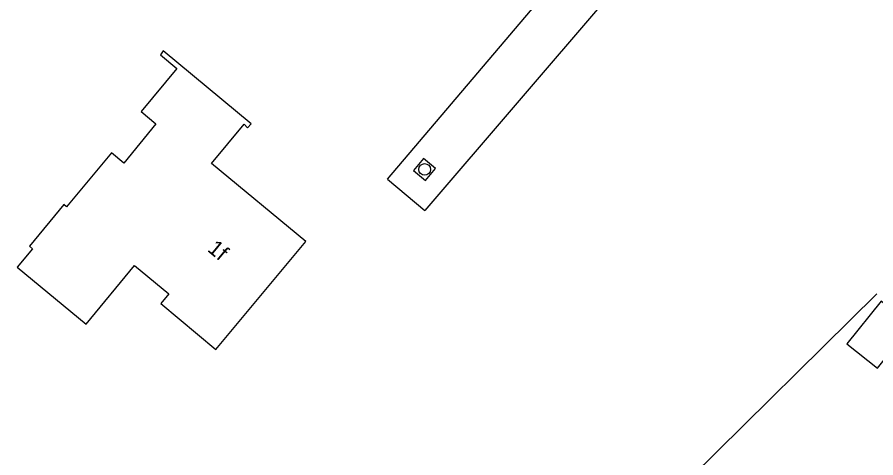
# Model space of a CAD drawing. Extents: x 136000 to 141000, y 400494 to 402006.
# Drawn here: x 137340.3 to 137395.2, y 401773.2 to 401801.4 of the extents above; entities that cross this region are included whole.
import ezdxf

# ---------------------------------------------------------------- set-up
doc = ezdxf.new("R2010")
doc.units = 0
for name, color, linetype in [('gg-afsc-hekwerk', 7, 'Continuous'), ('gg-anno-huisnummerreeks BGT', 7, 'Continuous'), ('gg-bbg-gedigitaliseerde bijgebouw', 7, 'Continuous'), ('gg-bbg-hoofdgebouw', 7, 'Continuous'), ('gg-knt-onverhard', 7, 'Continuous'), ('gt-grn-vlakafsluiter', 7, 'Continuous'), ('gt-symb-rioolschacht', 7, 'Continuous')]:
    doc.layers.add(name, color=color, linetype=linetype)

# ---------------------------------------------------------------- blocks, each defined once
blk = doc.blocks.new('gt0-RS')
at = {"layer": 'gt-symb-rioolschacht'}
blk.add_lwpolyline([(-0.5, -0.5), (0.5, -0.5), (0.5, 0.5), (-0.5, 0.5)], close=True, dxfattribs=at)
blk.add_circle((0, 0), 0.375, dxfattribs=at)

msp = doc.modelspace()

# ---------------------------------------------------------------- linework, layer by layer
at = {"layer": 'gg-afsc-hekwerk'}
msp.add_line((137383.216, 401771.789), (137395.278, 401783.691), dxfattribs=at)
at = {"layer": 'gg-bbg-gedigitaliseerde bijgebouw'}
msp.add_lwpolyline([(137395.543, 401783.222), (137393.354, 401780.491), (137395.305, 401778.928), (137397.494, 401781.659), (137395.543, 401783.222)], dxfattribs=at)
at = {"layer": 'gg-bbg-hoofdgebouw'}
msp.add_lwpolyline([(137341.064, 401786.745), (137341.239, 401786.578), (137340.265, 401785.388), (137344.676, 401781.751), (137347.768, 401785.5), (137349.966, 401783.687), (137349.464, 401783.078), (137352.971, 401780.122), (137358.743, 401787.038), (137352.698, 401792.04), (137354.78, 401794.542), (137355.013, 401794.323), (137355.241, 401794.567), (137349.598, 401799.252), (137349.427, 401798.997), (137350.481, 401798.118), (137348.194, 401795.356), (137349.134, 401794.578), (137347.089, 401792.061), (137346.305, 401792.714), (137343.426, 401789.26), (137343.256, 401789.4), (137341.064, 401786.745)], dxfattribs=at)
at = {"layer": 'gg-knt-onverhard'}
for p, q in [((137363.968, 401791.03), (137389.005, 401820.562)), ((137391.627, 401818.531), (137366.347, 401789.035))]:
    msp.add_line(p, q, dxfattribs=at)
at = {"layer": 'gt-grn-vlakafsluiter'}
msp.add_line((137363.968, 401791.03), (137366.347, 401789.035), dxfattribs=at)

# ---------------------------------------------------------------- block references
at = {"layer": 'gt-symb-rioolschacht', "rotation": 49.98904228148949}
msp.add_blockref('gt0-RS', (137366.336, 401791.655), dxfattribs=at)

# ---------------------------------------------------------------- texts
at = {"layer": 'gg-anno-huisnummerreeks BGT'}
msp.add_text('1f', height=1, rotation=320.4, dxfattribs=at).set_placement((137352.384, 401786.459))

doc.saveas('drawing.dxf')
